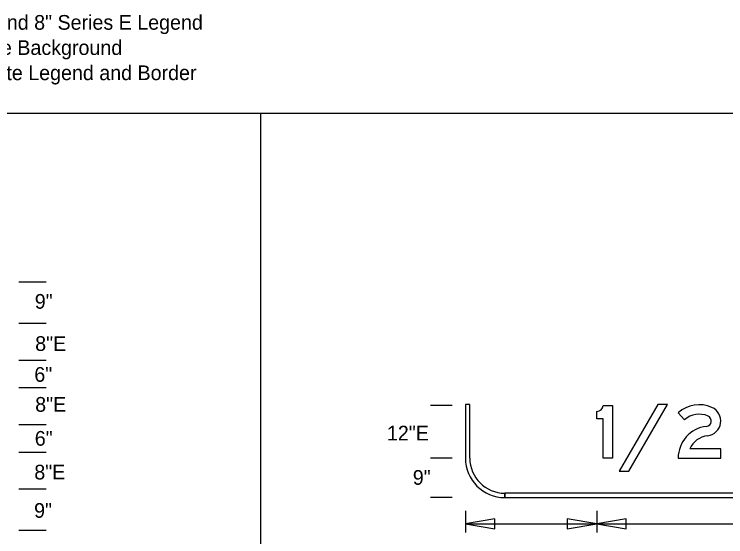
# Model space of a CAD drawing. Extents: x 0 to 770, y 0 to 495.
# Drawn here: x 208.7 to 378.2, y 229.1 to 353.5 of the extents above; entities that cross this region are included whole.
import ezdxf

# ---------------------------------------------------------------- set-up
doc = ezdxf.new("R2010")
doc.units = 0
for name, color, linetype in [('Core', 7, 'Continuous'), ('Default', 7, 'Continuous'), ('Dimension', 7, 'Continuous'), ('GSBWFill', 7, 'Continuous'), ('GSDims', 7, 'Continuous'), ('SheetLines_dp', 7, 'Continuous'), ('XSCell', 7, 'Continuous')]:
    doc.layers.add(name, color=color, linetype=linetype)

msp = doc.modelspace()

# ---------------------------------------------------------------- linework, layer by layer
at = {"layer": 'Core'}
for p, q in [((366.85, 258.64), (368.37, 256.97)), ((376.99, 250.1), (369.6, 250.1))]:
    msp.add_line(p, q, dxfattribs=at)
for points in [[(348.96, 260.36), (351.21, 260.36), (351.21, 247.84)], [(362.04, 260.59), (352.83, 244.72), (355.09, 244.72), (364.3, 260.59)], [(364.3, 260.59), (362.04, 260.59)], [(351.21, 247.84), (348.96, 247.84), (348.96, 257.23), (347.45, 257.23), (347.45, 258.98)], [(366.85, 247.84), (376.99, 247.84), (376.99, 250.1)]]:
    msp.add_lwpolyline(points, dxfattribs=at)
for centre, radius, start, end in [((347.45, 260.49), 1.51, 270, 355.0209), ((371.86, 253.13), 7.45, 66.0533, 132.3115), ((373.45, 256.7), 3.54, 276.6648, 66.0533), ((371.86, 253.13), 5.19, 66.0533, 132.3115), ((373.45, 256.7), 1.29, 276.6648, 66.0533), ((374.48, 247.84), 7.63, 96.6648, 180), ((374.48, 247.84), 5.38, 96.6648, 155.2535)]:
    msp.add_arc(centre, radius, start, end, dxfattribs=at)
at = {"layer": 'Dimension'}
for p, q in [((366.85, 258.64), (368.37, 256.97)), ((376.99, 250.1), (369.6, 250.1))]:
    msp.add_line(p, q, dxfattribs=at)
for points in [[(348.96, 260.36), (351.21, 260.36), (351.21, 247.84)], [(362.04, 260.59), (352.83, 244.72), (355.09, 244.72), (364.3, 260.59)], [(364.3, 260.59), (362.04, 260.59)], [(351.21, 247.84), (348.96, 247.84), (348.96, 257.23), (347.45, 257.23), (347.45, 258.98)], [(366.85, 247.84), (376.99, 247.84), (376.99, 250.1)]]:
    msp.add_lwpolyline(points, dxfattribs=at)
for points in [[(316.17, 232.2), (323.19, 231.01), (323.19, 233.39)], [(347.45, 232.2), (340.44, 233.39), (340.44, 231.01)], [(347.45, 232.2), (354.47, 231.01), (354.47, 233.39)]]:
    msp.add_lwpolyline(points, close=True, dxfattribs=at)
for centre, radius, start, end in [((347.45, 260.49), 1.51, 270, 355.0209), ((371.86, 253.13), 7.45, 66.0533, 132.3115), ((373.45, 256.7), 3.54, 276.6648, 66.0533), ((371.86, 253.13), 5.19, 66.0533, 132.3115), ((373.45, 256.7), 1.29, 276.6648, 66.0533), ((374.48, 247.84), 7.63, 96.6648, 180), ((374.48, 247.84), 5.38, 96.6648, 155.2535)]:
    msp.add_arc(centre, radius, start, end, dxfattribs=at)
at = {"layer": 'GSBWFill'}
for p, q in [((316.17, 260.59), (316.17, 247.84)), ((316.17, 260.59), (316.17, 247.84)), ((317.21, 247.84), (317.21, 260.59)), ((325.56, 238.46), (325.56, 239.5)), ((444.43, 239.5), (325.57, 239.5)), ((325.57, 239.5), (325.57, 238.46)), ((325.56, 238.46), (444.43, 238.46)), ((325.57, 238.46), (444.43, 238.46))]:
    msp.add_line(p, q, dxfattribs=at)
msp.add_lwpolyline([(317.21, 260.59), (316.17, 260.59)], dxfattribs=at)
for radius in [9.39, 9.39, 8.34]:
    msp.add_arc((325.56, 247.84), radius, 180, 270, dxfattribs=at)
at = {"layer": 'GSDims'}
for p, q in [((209.86, 289.81), (216.32, 289.81)), ((209.86, 279.96), (216.32, 279.96)), ((209.86, 279.96), (216.32, 279.96)), ((209.86, 271.2), (216.32, 271.2)), ((209.86, 271.2), (216.32, 271.2)), ((209.86, 264.63), (216.32, 264.63)), ((209.86, 264.63), (216.32, 264.63)), ((313.04, 260.36), (307.83, 260.36)), ((313.04, 260.36), (307.83, 260.36)), ((209.86, 255.88), (216.32, 255.88)), ((209.86, 255.88), (216.32, 255.88)), ((209.86, 249.31), (216.32, 249.31)), ((209.86, 249.31), (216.32, 249.31)), ((313.04, 247.84), (307.83, 247.84)), ((313.04, 247.84), (307.83, 247.84)), ((209.86, 240.56), (216.32, 240.56)), ((209.86, 240.56), (216.32, 240.56)), ((313.04, 238.46), (307.83, 238.46)), ((316.17, 235.33), (316.17, 230.12)), ((347.45, 235.33), (347.45, 230.12)), ((347.45, 235.33), (347.45, 230.12)), ((316.17, 232.2), (347.45, 232.2)), ((347.45, 232.2), (422.54, 232.2)), ((209.86, 230.7), (216.32, 230.7))]:
    msp.add_line(p, q, dxfattribs=at)
at = {"layer": 'SheetLines_dp'}
for p, q in [((0, 330), (770, 330)), ((267.49, 0), (267.49, 330))]:
    msp.add_line(p, q, dxfattribs=at)
at = {"layer": 'XSCell'}
for p, q in [((366.85, 258.64), (368.37, 256.97)), ((376.99, 250.1), (369.6, 250.1))]:
    msp.add_line(p, q, dxfattribs=at)
for points in [[(348.96, 260.36), (351.21, 260.36), (351.21, 247.84)], [(362.04, 260.59), (352.83, 244.72), (355.09, 244.72), (364.3, 260.59)], [(364.3, 260.59), (362.04, 260.59)], [(351.21, 247.84), (348.96, 247.84), (348.96, 257.23), (347.45, 257.23), (347.45, 258.98)], [(366.85, 247.84), (376.99, 247.84), (376.99, 250.1)]]:
    msp.add_lwpolyline(points, dxfattribs=at)
for centre, radius, start, end in [((347.45, 260.49), 1.51, 270, 355.0209), ((371.86, 253.13), 7.45, 66.0533, 132.3115), ((373.45, 256.7), 3.54, 276.6648, 66.0533), ((371.86, 253.13), 5.19, 66.0533, 132.3115), ((373.45, 256.7), 1.29, 276.6648, 66.0533), ((374.48, 247.84), 7.63, 96.6648, 180), ((374.48, 247.84), 5.38, 96.6648, 155.2535)]:
    msp.add_arc(centre, radius, start, end, dxfattribs=at)

# ---------------------------------------------------------------- texts
at = {"layer": 'Default'}
for s, p in [('6" and 8" Series E Legend', (198.81, 349.84)), ('Blue Background', (198.81, 343.84)), ('White Legend and Border', (198.81, 337.84)), ('9"', (213.63, 283.42)), ('8"E', (213.73, 273.38)), ('6"', (213.52, 266.03)), ('8"E', (213.73, 258.9)), ('6"', (213.63, 250.81)), ('12"E', (297.49, 252.06)), ('8"E', (213.52, 242.78)), ('9"', (303.65, 241.51)), ('9"', (213.47, 233.65))]:
    msp.add_text(s, height=3.5, dxfattribs=at).set_placement(p)

doc.saveas('drawing.dxf')
